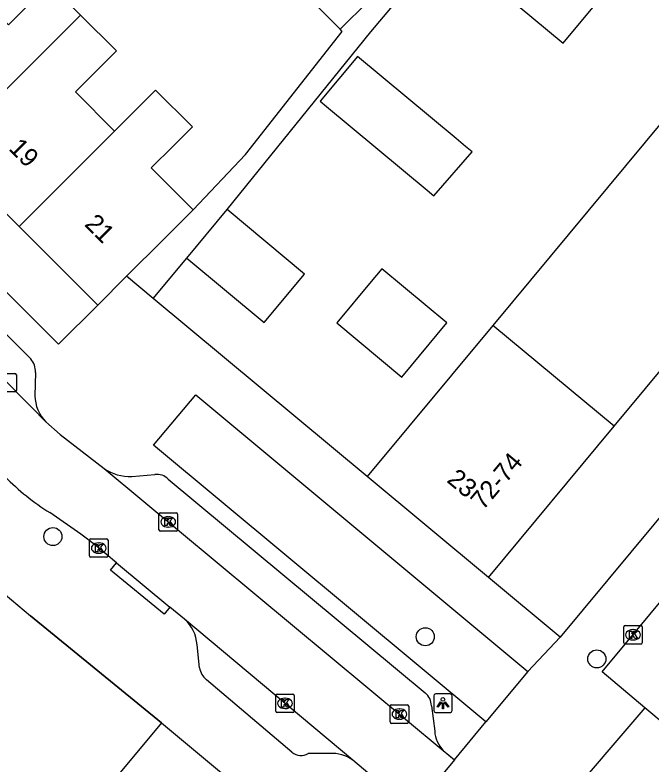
# Model space of a CAD drawing. Extents: x 162532 to 163264, y 381233 to 382042.
# Drawn here: x 162920.22 to 162954.65, y 381623.51 to 381664.1 of the extents above; entities that cross this region are included whole.
import ezdxf

# ---------------------------------------------------------------- set-up
doc = ezdxf.new("R2010")
doc.units = 0
for name, color, linetype in [('IMGEO_Boom', 7, 'Continuous'), ('IMGEO_Kolk', 7, 'Continuous'), ('IMGEO_Lichtpunt', 7, 'Continuous'), ('IMGEO_Muur', 7, 'Continuous'), ('IMGEO_Pand', 7, 'Continuous'), ('IMGEO_Pand_nummerreeks', 7, 'Continuous'), ('IMGEO_Rijbaan_lokaal_open', 7, 'Continuous'), ('IMGEO_Voetpad_open', 7, 'Continuous')]:
    doc.layers.add(name, color=color, linetype=linetype)

msp = doc.modelspace()

# ---------------------------------------------------------------- linework, layer by layer
at = {"layer": 'IMGEO_Boom'}
for centre in [(162922.272, 381635.876), (162942.432, 381630.451), (162951.717, 381629.255)]:
    msp.add_circle(centre, 0.489, dxfattribs=at)
at = {"layer": 'IMGEO_Kolk'}
for p, q in [((162919.37, 381644.707), (162920.222, 381644.707)), ((162920.296, 381644.633), (162920.296, 381643.781)), ((162920.222, 381643.707), (162919.37, 381643.707)), ((162928.015, 381636.242), (162928.015, 381637.094)), ((162928.09, 381637.168), (162928.942, 381637.168)), ((162928.503, 381636.948), (162928.528, 381636.948)), ((162929.016, 381637.094), (162929.016, 381636.242)), ((162928.942, 381636.168), (162928.09, 381636.168)), ((162928.526, 381636.388), (162928.501, 381636.388)), ((162924.258, 381634.826), (162924.258, 381635.678)), ((162924.333, 381635.752), (162925.185, 381635.752)), ((162925.259, 381635.678), (162925.259, 381634.826)), ((162924.746, 381635.532), (162924.771, 381635.532)), ((162924.769, 381634.972), (162924.744, 381634.972)), ((162925.185, 381634.752), (162924.333, 381634.752)), ((162953.173, 381630.131), (162953.173, 381630.983)), ((162953.248, 381631.057), (162954.1, 381631.057)), ((162953.661, 381630.837), (162953.686, 381630.837)), ((162954.174, 381630.983), (162954.174, 381630.131)), ((162954.1, 381630.057), (162953.248, 381630.057)), ((162953.684, 381630.277), (162953.659, 381630.277)), ((162934.334, 381626.423), (162934.334, 381627.275)), ((162934.409, 381627.349), (162935.261, 381627.349)), ((162934.822, 381627.129), (162934.847, 381627.129)), ((162935.335, 381627.275), (162935.335, 381626.423)), ((162940.534, 381625.841), (162940.534, 381626.693)), ((162940.609, 381626.767), (162941.461, 381626.767)), ((162941.535, 381626.693), (162941.535, 381625.841)), ((162935.261, 381626.349), (162934.409, 381626.349)), ((162934.845, 381626.569), (162934.82, 381626.569)), ((162941.022, 381626.547), (162941.047, 381626.547)), ((162941.045, 381625.987), (162941.02, 381625.987)), ((162941.461, 381625.767), (162940.609, 381625.767))]:
    msp.add_line(p, q, dxfattribs=at)
for points in [[(162919.37, 381644.707), (162920.222, 381644.707)], [(162920.296, 381644.633), (162920.296, 381643.781)], [(162920.222, 381643.707), (162919.37, 381643.707)], [(162928.015, 381636.242), (162928.015, 381637.094)], [(162928.09, 381637.168), (162928.942, 381637.168)], [(162928.336, 381636.868), (162928.459, 381636.868), (162928.459, 381636.717), (162928.589, 381636.868), (162928.753, 381636.868), (162928.607, 381636.717), (162928.76, 381636.468), (162928.608, 381636.468), (162928.523, 381636.632), (162928.459, 381636.565), (162928.459, 381636.468), (162928.336, 381636.468), (162928.336, 381636.868)], [(162929.016, 381637.094), (162929.016, 381636.242)], [(162928.942, 381636.168), (162928.09, 381636.168)], [(162924.258, 381634.826), (162924.258, 381635.678)], [(162924.333, 381635.752), (162925.185, 381635.752)], [(162925.259, 381635.678), (162925.259, 381634.826)], [(162924.579, 381635.452), (162924.702, 381635.452), (162924.702, 381635.301), (162924.832, 381635.452), (162924.996, 381635.452), (162924.85, 381635.301), (162925.003, 381635.052), (162924.851, 381635.052), (162924.766, 381635.216), (162924.702, 381635.149), (162924.702, 381635.052), (162924.579, 381635.052), (162924.579, 381635.452)], [(162925.185, 381634.752), (162924.333, 381634.752)], [(162953.173, 381630.131), (162953.173, 381630.983)], [(162953.248, 381631.057), (162954.1, 381631.057)], [(162953.494, 381630.757), (162953.617, 381630.757), (162953.617, 381630.606), (162953.747, 381630.757), (162953.911, 381630.757), (162953.765, 381630.606), (162953.918, 381630.357), (162953.766, 381630.357), (162953.681, 381630.521), (162953.617, 381630.454), (162953.617, 381630.357), (162953.494, 381630.357), (162953.494, 381630.757)], [(162954.174, 381630.983), (162954.174, 381630.131)], [(162954.1, 381630.057), (162953.248, 381630.057)], [(162934.334, 381626.423), (162934.334, 381627.275)], [(162934.409, 381627.349), (162935.261, 381627.349)], [(162935.335, 381627.275), (162935.335, 381626.423)], [(162934.655, 381627.049), (162934.778, 381627.049), (162934.778, 381626.898), (162934.908, 381627.049), (162935.072, 381627.049), (162934.926, 381626.898), (162935.079, 381626.649), (162934.927, 381626.649), (162934.842, 381626.813), (162934.778, 381626.746), (162934.778, 381626.649), (162934.655, 381626.649), (162934.655, 381627.049)], [(162940.534, 381625.841), (162940.534, 381626.693)], [(162940.609, 381626.767), (162941.461, 381626.767)], [(162941.535, 381626.693), (162941.535, 381625.841)], [(162935.261, 381626.349), (162934.409, 381626.349)], [(162940.855, 381626.467), (162940.978, 381626.467), (162940.978, 381626.316), (162941.108, 381626.467), (162941.272, 381626.467), (162941.126, 381626.316), (162941.279, 381626.067), (162941.127, 381626.067), (162941.042, 381626.231), (162940.978, 381626.164), (162940.978, 381626.067), (162940.855, 381626.067), (162940.855, 381626.467)], [(162941.461, 381625.767), (162940.609, 381625.767)]]:
    msp.add_lwpolyline(points, dxfattribs=at)
for centre, start, end in [((162920.22, 381644.631), 1.552, 88.448), ((162920.22, 381644.631), 1.552, 88.448), ((162920.22, 381643.783), 271.552, 358.448), ((162920.22, 381643.783), 271.552, 358.448), ((162928.092, 381637.092), 91.552, 178.448), ((162928.092, 381637.092), 91.552, 178.448), ((162928.94, 381637.092), 1.552, 88.448), ((162928.94, 381637.092), 1.552, 88.448), ((162928.092, 381636.244), 181.552, 268.448), ((162928.092, 381636.244), 181.552, 268.448), ((162928.94, 381636.244), 271.552, 358.448), ((162928.94, 381636.244), 271.552, 358.448), ((162924.335, 381635.676), 91.552, 178.448), ((162924.335, 381635.676), 91.552, 178.448), ((162925.183, 381635.676), 1.552, 88.448), ((162925.183, 381635.676), 1.552, 88.448), ((162924.335, 381634.828), 181.552, 268.448), ((162924.335, 381634.828), 181.552, 268.448), ((162925.183, 381634.828), 271.552, 358.448), ((162925.183, 381634.828), 271.552, 358.448), ((162953.25, 381630.981), 91.552, 178.448), ((162953.25, 381630.981), 91.552, 178.448), ((162954.098, 381630.981), 1.552, 88.448), ((162954.098, 381630.981), 1.552, 88.448), ((162953.25, 381630.133), 181.552, 268.448), ((162953.25, 381630.133), 181.552, 268.448), ((162954.098, 381630.133), 271.552, 358.448), ((162954.098, 381630.133), 271.552, 358.448), ((162934.411, 381627.273), 91.552, 178.448), ((162934.411, 381627.273), 91.552, 178.448), ((162935.259, 381627.273), 1.552, 88.448), ((162935.259, 381627.273), 1.552, 88.448), ((162940.611, 381626.691), 91.552, 178.448), ((162940.611, 381626.691), 91.552, 178.448), ((162941.459, 381626.691), 1.552, 88.448), ((162941.459, 381626.691), 1.552, 88.448), ((162934.411, 381626.425), 181.552, 268.448), ((162934.411, 381626.425), 181.552, 268.448), ((162935.259, 381626.425), 271.552, 358.448), ((162935.259, 381626.425), 271.552, 358.448), ((162940.611, 381625.843), 181.552, 268.448), ((162940.611, 381625.843), 181.552, 268.448), ((162941.459, 381625.843), 271.552, 358.448), ((162941.459, 381625.843), 271.552, 358.448)]:
    msp.add_arc(centre, 0.0765, start, end, dxfattribs=at)
for centre, major_axis, ratio, start_param, end_param in [((162928.502, 381636.668), (-0.387, 0.002), 0.722429, 4.712389, 7.853982), ((162928.527, 381636.668), (-0.39, 0.002), 0.717154, 1.570796, 4.712389), ((162924.745, 381635.252), (-0.387, 0.002), 0.722429, 4.712389, 7.853982), ((162924.77, 381635.252), (-0.39, 0.002), 0.717154, 1.570796, 4.712389), ((162953.66, 381630.557), (-0.387, 0.002), 0.722429, 4.712389, 7.853982), ((162953.685, 381630.557), (-0.39, 0.002), 0.717154, 1.570796, 4.712389), ((162934.821, 381626.849), (-0.387, 0.002), 0.722429, 4.712389, 7.853982), ((162934.846, 381626.849), (-0.39, 0.002), 0.717154, 1.570796, 4.712389), ((162941.021, 381626.267), (-0.387, 0.002), 0.722429, 4.712389, 7.853982), ((162941.046, 381626.267), (-0.39, 0.002), 0.717154, 1.570796, 4.712389)]:
    msp.add_ellipse(centre, major_axis=major_axis, ratio=ratio, start_param=start_param, end_param=end_param, dxfattribs=at)
at = {"layer": 'IMGEO_Lichtpunt'}
for p, q in [((162942.889, 381627.26), (162942.889, 381626.453)), ((162942.889, 381627.26), (162942.889, 381626.453)), ((162943.791, 381627.355), (162942.983, 381627.355)), ((162943.791, 381627.355), (162942.983, 381627.355)), ((162943.885, 381626.453), (162943.885, 381627.26)), ((162943.885, 381626.453), (162943.885, 381627.26)), ((162942.983, 381626.359), (162943.791, 381626.359)), ((162942.983, 381626.359), (162943.791, 381626.359))]:
    msp.add_line(p, q, dxfattribs=at)
for points in [[(162943.263, 381626.924), (162943.302, 381626.896), (162943.114, 381626.634), (162943.076, 381626.661), (162943.263, 381626.924)], [(162943.365, 381626.876), (162943.412, 381626.876), (162943.412, 381626.554), (162943.365, 381626.554), (162943.365, 381626.876)], [(162943.475, 381626.896), (162943.513, 381626.923), (162943.7, 381626.661), (162943.661, 381626.633), (162943.475, 381626.896)]]:
    msp.add_lwpolyline(points, dxfattribs=at)
msp.add_circle((162943.388, 381627.058), 0.0994, dxfattribs=at)
for centre, start, end in [((162942.983, 381627.26), 90, 180), ((162942.983, 381627.26), 90, 180), ((162943.791, 381627.26), 0, 90), ((162943.791, 381627.26), 0, 90), ((162942.983, 381626.453), 180, 270), ((162942.983, 381626.453), 180, 270), ((162943.791, 381626.453), 270, 0), ((162943.791, 381626.453), 270, 360)]:
    msp.add_arc(centre, 0.0946, start, end, dxfattribs=at)
at = {"layer": 'IMGEO_Muur'}
for points in [[(162939.283, 381639.132), (162927.706, 381648.764)], [(162928.147, 381625.792), (162921.065, 381631.586)]]:
    msp.add_lwpolyline(points, dxfattribs=at)
at = {"layer": 'IMGEO_Pand'}
for points in [[(162945.887, 381670.296), (162943.737, 381667.712), (162944.172, 381667.35), (162949.895, 381662.587), (162952.045, 381665.171), (162946.322, 381669.934), (162945.887, 381670.296)], [(162936.018, 381668.212), (162939.352, 381664.851), (162937.823, 381663.334)], [(162937.823, 381663.334), (162934.495, 381666.69)], [(162917.484, 381665.947), (162919.867, 381663.564), (162920.263, 381663.959), (162922.089, 381665.783), (162923.771, 381664.101)], [(162923.771, 381664.101), (162921.63, 381661.962), (162916.563, 381656.899), (162916.385, 381656.722)], [(162923.771, 381664.101), (162925.713, 381662.158), (162924.578, 381661.024), (162923.492, 381659.939), (162925.615, 381657.817)], [(162959.478, 381663.4), (162946.086, 381647.307)], [(162942.539, 381654.618), (162942.899, 381654.319), (162944.971, 381656.703), (162944.602, 381656.992), (162944.111, 381657.419), (162938.77, 381661.86), (162936.75, 381659.432), (162937.084, 381659.154), (162942.539, 381654.618)], [(162925.615, 381657.817), (162927.836, 381660.036), (162929.823, 381658.048), (162928.796, 381657.022), (162927.602, 381655.829), (162929.867, 381653.565)], [(162952.658, 381641.842), (162966.045, 381657.938)], [(162920.45, 381652.657), (162920.626, 381652.832), (162925.615, 381657.817)], [(162916.385, 381656.722), (162916.456, 381656.651), (162920.379, 381652.728), (162920.45, 381652.657)], [(162929.867, 381653.565), (162928.24, 381651.939), (162926.264, 381649.964)], [(162929.521, 381650.946), (162931.702, 381653.568)], [(162929.521, 381650.946), (162933.711, 381647.461), (162935.892, 381650.083), (162931.702, 381653.568)], [(162920.45, 381652.657), (162924.703, 381648.404)], [(162939.505, 381649.687), (162937.636, 381647.44), (162941.164, 381644.507), (162943.601, 381647.438), (162940.074, 381650.371), (162939.505, 381649.687)], [(162926.264, 381649.964), (162924.703, 381648.404)], [(162946.086, 381647.307), (162939.283, 381639.132)], [(162952.658, 381641.842), (162946.086, 381647.307)], [(162945.856, 381633.664), (162952.658, 381641.842)], [(162945.856, 381633.664), (162939.283, 381639.132)], [(162928.147, 381625.792), (162921.421, 381617.708)], [(162928.147, 381625.792), (162934.732, 381620.307)]]:
    msp.add_lwpolyline(points, dxfattribs=at)
at = {"layer": 'IMGEO_Rijbaan_lokaal_open'}
for points in [[(162954.316, 381626.612), (162952.008, 381628.554), (162975.131, 381656.377)], [(162921.894, 381642.081), (162921.134, 381642.861), (162916.129, 381647.892)], [(162921.894, 381642.081), (162922.663, 381641.401), (162925.045, 381639.55)], [(162925.045, 381639.55), (162943.398, 381624.302)], [(162925.718, 381634.445), (162924.592, 381635.395), (162923.792, 381636.009), (162922.11, 381637.169)], [(162925.718, 381634.445), (162928.612, 381632.057)], [(162929.391, 381631.408), (162928.612, 381632.057)], [(162938.502, 381623.781), (162929.391, 381631.408)], [(162957.121, 381625.277), (162956.912, 381625.027), (162956.624, 381624.669), (162954.316, 381626.612)], [(162943.398, 381624.302), (162943.706, 381624.046), (162944.009, 381623.798)], [(162941.732, 381621.049), (162938.502, 381623.781)], [(162944.009, 381623.798), (162941.732, 381621.049)]]:
    msp.add_lwpolyline(points, dxfattribs=at)
msp.add_arc((162929.201, 381648.48), 13.35, 224.5469, 237.9147, dxfattribs=at)
at = {"layer": 'IMGEO_Voetpad_open'}
for points in [[(162924.703, 381648.404), (162922.581, 381646.284), (162881.716, 381687.133), (162883.851, 381689.256)], [(162931.702, 381653.568), (162939.489, 381663.184), (162947.805, 381673.057), (162951.04, 381675.633)], [(162929.867, 381653.565), (162932.708, 381656.555), (162937.94, 381663.216), (162937.823, 381663.334)], [(162976.513, 381662.626), (162949.739, 381630.435)], [(162927.706, 381648.764), (162929.521, 381650.946)], [(162927.706, 381648.764), (162926.264, 381649.964)], [(162917.5, 381649.027), (162921.079, 381645.492)], [(162939.283, 381639.132), (162927.706, 381648.764)], [(162921.334, 381644.757), (162921.292, 381643.5)], [(162945.701, 381625.847), (162927.728, 381640.815), (162930.014, 381643.539), (162947.985, 381628.574)], [(162926.538, 381639.132), (162927.793, 381639.233)], [(162928.514, 381638.984), (162942.421, 381627.412)], [(162916.591, 381635.339), (162921.065, 381631.586), (162928.147, 381625.792)], [(162928.612, 381632.057), (162928.294, 381631.672), (162925.4, 381634.06), (162925.718, 381634.445)], [(162949.739, 381630.435), (162945.856, 381633.664)], [(162947.985, 381628.574), (162949.739, 381630.435)], [(162930.208, 381628.775), (162930.079, 381630.023)], [(162947.985, 381628.574), (162945.701, 381625.847)], [(162935.214, 381624.204), (162930.589, 381628.121)], [(162942.765, 381626.714), (162942.941, 381625.35)], [(162954.316, 381626.612), (162949.795, 381621.313)], [(162944.009, 381623.798), (162945.701, 381625.847)], [(162937.27, 381624.135), (162936.096, 381624.129)]]:
    msp.add_lwpolyline(points, dxfattribs=at)
for centre, radius, start, end in [((162920.207, 381644.778), 1.127, 358.9431, 39.3242), ((162923.462, 381643.583), 2.172, 182.2031, 223.7743), ((162926.43, 381641.622), 2.492, 236.2374, 272.481), ((162927.899, 381638.371), 0.868, 44.8967, 96.9982), ((162928.066, 381629.887), 2.017, 3.8789, 48.953), ((162931.316, 381628.982), 1.127, 190.6053, 229.8422), ((162941.862, 381626.703), 0.903, 0.7184, 51.7531), ((162944.609, 381625.454), 1.672, 183.5644, 223.5566), ((162935.705, 381624.757), 0.74, 228.3957, 301.8835), ((162937.401, 381622.27), 1.869, 53.9149, 94.0224)]:
    msp.add_arc(centre, radius, start, end, dxfattribs=at)

# ---------------------------------------------------------------- texts
at = {"layer": 'IMGEO_Pand_nummerreeks'}
for s, rotation, p in [('19', 315, (162919.838, 381656.834)), ('21', 315, (162923.938, 381652.733)), ('72-74', 50.0636, (162945.565, 381637.261)), ('23', 320.2433, (162943.546, 381638.864))]:
    msp.add_text(s, height=1, rotation=rotation, dxfattribs=at).set_placement(p)

doc.saveas('drawing.dxf')
